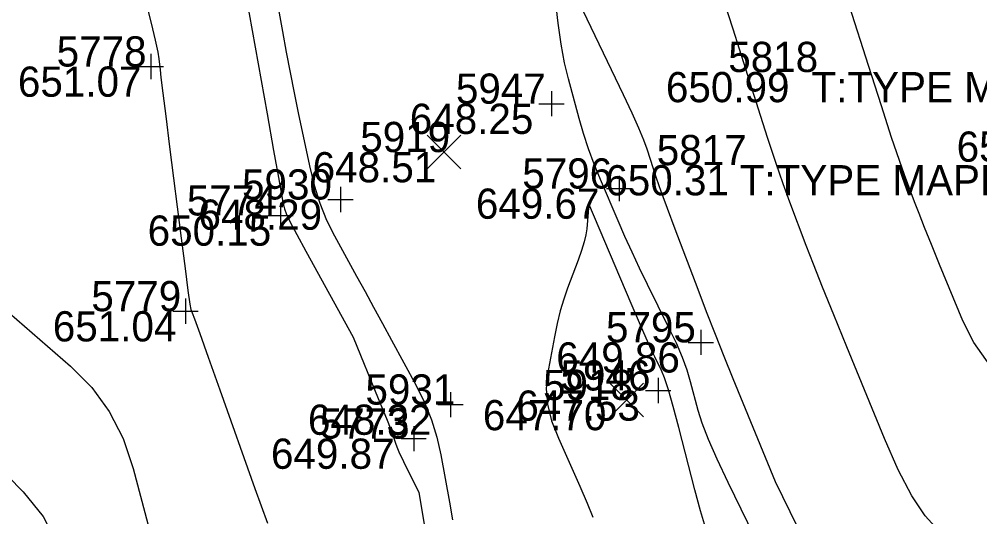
# Model space of a CAD drawing. Extents: x 2129350 to 2137777, y 657588 to 659885.
# Drawn here: x 2132814.87 to 2132853.02, y 658908.72 to 658928.49 of the extents above; entities that cross this region are included whole.
import ezdxf

# ---------------------------------------------------------------- set-up
doc = ezdxf.new("R2010")
doc.units = 0
for name, color, linetype in [('DT_X_Contour_Major', 7, 'Continuous'), ('DT_X_Contour_Minor', 7, 'Continuous'), ('SV_X_Random_Point', 7, 'Continuous'), ('SV_X_Shot_Marker', 7, 'Continuous'), ('SV_X_Text_Comment', 7, 'Continuous'), ('SV_X_Text_Elevation', 7, 'Continuous'), ('SV_X_Text_Name', 7, 'Continuous')]:
    doc.layers.add(name, color=color, linetype=linetype)

msp = doc.modelspace()

# ---------------------------------------------------------------- linework, layer by layer
at = {"layer": 'DT_X_Contour_Major'}
for points in [[(2132823.644, 658930.703), (2132824.713, 658924.723), (2132824.973, 658923.27), (2132825.166, 658922.202), (2132825.29, 658921.52), (2132825.346, 658921.223), (2132825.404, 658920.947), (2132825.473, 658920.765), (2132825.638, 658920.425), (2132825.898, 658919.928), (2132826.254, 658919.274), (2132828.135, 658915.855), (2132829.132, 658913.416), (2132829.327, 658912.937), (2132829.482, 658912.549), (2132829.599, 658912.25), (2132829.677, 658912.04), (2132829.833, 658911.601), (2132829.899, 658911.428), (2132829.98, 658911.236), (2132830.076, 658911.027), (2132830.188, 658910.8), (2132830.742, 658909.698), (2132831.737, 658903.676)], [(2132847.236, 658905.332), (2132844.904, 658910.111), (2132843.227, 658914.201), (2132842.87, 658915.08), (2132842.519, 658915.965), (2132842.172, 658916.855), (2132841.831, 658917.752), (2132840.928, 658920.149), (2132840.62, 658920.972), (2132840.373, 658921.645), (2132840.187, 658922.166), (2132840.063, 658922.536), (2132839.813, 658923.322), (2132839.684, 658923.678), (2132839.485, 658924.157), (2132839.214, 658924.758), (2132838.872, 658925.483), (2132837.114, 658929.15)]]:
    msp.add_lwpolyline(points, dxfattribs=at)
at = {"layer": 'DT_X_Contour_Minor'}
for points in [[(2132853.415, 658914.744), (2132852.783, 658915.644), (2132852.343, 658916.504), (2132851.423, 658918.746), (2132851.103, 658919.532), (2132850.831, 658920.208), (2132850.607, 658920.773), (2132850.432, 658921.229), (2132850.029, 658922.298), (2132849.827, 658922.87), (2132849.521, 658923.785), (2132849.112, 658925.043), (2132848.601, 658926.645), (2132847.098, 658931.373)], [(2132824.93, 658930.201), (2132825.324, 658928), (2132825.474, 658927.18), (2132825.629, 658926.367), (2132825.788, 658925.564), (2132825.952, 658924.769), (2132826.396, 658922.662), (2132826.583, 658921.895), (2132826.811, 658921.176), (2132827.08, 658920.505), (2132827.39, 658919.881), (2132828.27, 658918.281), (2132828.605, 658917.672), (2132828.948, 658917.044), (2132829.299, 658916.397), (2132829.659, 658915.732), (2132830.631, 658913.933), (2132830.966, 658913.255), (2132831.242, 658912.569), (2132831.459, 658911.875), (2132831.616, 658911.173), (2132831.958, 658909.293), (2132832.085, 658908.589)], [(2132819.89, 658929.221), (2132820.11, 658928.336), (2132820.272, 658927.656), (2132820.376, 658927.183), (2132820.422, 658926.916), (2132820.466, 658926.478), (2132820.502, 658926.164), (2132820.577, 658925.549), (2132820.691, 658924.635), (2132820.843, 658923.421), (2132821.303, 658919.783), (2132821.457, 658918.583), (2132821.572, 658917.711), (2132821.65, 658917.167), (2132821.69, 658916.952), (2132821.747, 658916.814), (2132821.83, 658916.585), (2132822.04, 658916), (2132822.374, 658915.061), (2132822.835, 658913.766), (2132824.229, 658909.841), (2132824.733, 658908.461)], [(2132844.331, 658907.411), (2132843.032, 658910.075), (2132842.591, 658911.003), (2132842.245, 658911.788), (2132841.993, 658912.432), (2132841.835, 658912.933), (2132841.538, 658914.079), (2132841.401, 658914.536), (2132841.211, 658915.046), (2132840.97, 658915.611), (2132840.676, 658916.229), (2132839.822, 658917.948), (2132839.509, 658918.59), (2132839.211, 658919.224), (2132838.926, 658919.852), (2132838.656, 658920.472), (2132837.954, 658922.118), (2132837.703, 658922.732), (2132837.479, 658923.34), (2132837.28, 658923.942), (2132837.108, 658924.538), (2132836.682, 658926.119), (2132836.529, 658926.759), (2132836.392, 658927.494), (2132836.27, 658928.323), (2132836.164, 658929.246)], [(2132853.21, 658906.49), (2132852.734, 658906.955), (2132851.371, 658908.18), (2132850.854, 658908.753), (2132850.325, 658909.552), (2132849.784, 658910.576), (2132849.231, 658911.827), (2132847.74, 658915.463), (2132847.22, 658916.738), (2132846.778, 658917.834), (2132846.416, 658918.751), (2132846.131, 658919.49), (2132845.479, 658921.223), (2132845.217, 658921.941), (2132844.922, 658922.794), (2132844.593, 658923.784), (2132844.231, 658924.909), (2132843.22, 658928.09), (2132842.863, 658929.187)], [(2132842.121, 658908.285), (2132841.93, 658908.948), (2132841.707, 658909.787), (2132841.067, 658912.262), (2132840.844, 658913.1), (2132840.655, 658913.757), (2132840.502, 658914.233), (2132840.382, 658914.529), (2132840.11, 658915.078), (2132839.976, 658915.364), (2132839.776, 658915.811), (2132839.511, 658916.419), (2132839.181, 658917.187), (2132837.49, 658921.151), (2132837.414, 658920.161), (2132837.38, 658919.923), (2132837.311, 658919.635), (2132837.207, 658919.296), (2132837.068, 658918.907), (2132836.65, 658917.801), (2132836.499, 658917.369), (2132836.362, 658916.901), (2132836.238, 658916.399), (2132836.127, 658915.861), (2132835.849, 658914.379), (2132835.798, 658913.804), (2132835.854, 658913.188), (2132836.016, 658912.532), (2132836.284, 658911.836), (2132837.143, 658909.927), (2132837.43, 658909.263), (2132837.649, 658908.704)], [(2132814.476, 658916.823), (2132816.912, 658914.706), (2132817.753, 658913.856), (2132818.447, 658912.895), (2132818.995, 658911.823), (2132819.396, 658910.64), (2132820.273, 658907.335)], [(2132813.808, 658910.945), (2132815.032, 658909.71), (2132815.829, 658908.733), (2132816.199, 658908.013)]]:
    msp.add_lwpolyline(points, dxfattribs=at)
at = {"layer": 'SV_X_Random_Point'}
for p, q in [((2132831.075, 658922.539), (2132832.409, 658923.875)), ((2132831.075, 658923.875), (2132832.409, 658922.539)), ((2132838.334, 658912.688), (2132839.668, 658914.022)), ((2132838.334, 658914.022), (2132839.668, 658912.688))]:
    msp.add_line(p, q, dxfattribs=at)
at = {"layer": 'SV_X_Shot_Marker'}
for p, q in [((2132820.101, 658927.106), (2132820.101, 658926.106)), ((2132819.601, 658926.606), (2132820.601, 658926.606)), ((2132820.101, 658926.606), (2132820.101, 658926.606)), ((2132836.013, 658925.629), (2132836.013, 658924.629)), ((2132835.513, 658925.129), (2132836.513, 658925.129)), ((2132836.013, 658925.129), (2132836.013, 658925.129)), ((2132838.696, 658922.258), (2132838.696, 658921.258)), ((2132827.633, 658921.822), (2132827.633, 658920.822)), ((2132838.196, 658921.758), (2132839.196, 658921.758)), ((2132838.696, 658921.758), (2132838.696, 658921.758)), ((2132825.254, 658921.188), (2132825.254, 658920.188)), ((2132827.133, 658921.322), (2132828.133, 658921.322)), ((2132827.633, 658921.322), (2132827.633, 658921.322)), ((2132824.754, 658920.688), (2132825.754, 658920.688)), ((2132825.254, 658920.688), (2132825.254, 658920.688)), ((2132821.478, 658917.384), (2132821.478, 658916.384)), ((2132820.978, 658916.884), (2132821.978, 658916.884)), ((2132821.478, 658916.884), (2132821.478, 658916.884)), ((2132841.945, 658916.147), (2132841.945, 658915.147)), ((2132841.445, 658915.647), (2132842.445, 658915.647)), ((2132841.945, 658915.647), (2132841.945, 658915.647)), ((2132840.245, 658914.234), (2132840.245, 658913.234)), ((2132831.997, 658913.674), (2132831.997, 658912.674)), ((2132839.745, 658913.734), (2132840.745, 658913.734)), ((2132840.245, 658913.734), (2132840.245, 658913.734)), ((2132831.497, 658913.174), (2132832.497, 658913.174)), ((2132831.997, 658913.174), (2132831.997, 658913.174)), ((2132830.539, 658912.323), (2132830.539, 658911.323)), ((2132830.039, 658911.823), (2132831.039, 658911.823)), ((2132830.539, 658911.823), (2132830.539, 658911.823))]:
    msp.add_line(p, q, dxfattribs=at)

# ---------------------------------------------------------------- texts
at = {"layer": 'SV_X_Text_Comment'}
for p in [(2132846.338, 658925.188), (2132843.488, 658921.488)]:
    msp.add_text('T:TYPE MAPLE T:PHOTO', height=1.2, dxfattribs=at).set_placement(p)
at = {"layer": 'SV_X_Text_Elevation'}
for s, p in [('651.07', (2132814.82, 658925.406)), ('650.99', (2132840.556, 658925.188)), ('648.25', (2132830.382, 658923.929)), ('653.61', (2132852.102, 658922.825)), ('648.51', (2132826.526, 658922.007)), ('650.31', (2132838.149, 658921.488)), ('649.67', (2132833.008, 658920.558)), ('648.29', (2132821.992, 658920.122)), ('650.15', (2132819.973, 658919.488)), ('651.04', (2132816.206, 658915.684)), ('649.86', (2132836.201, 658914.447)), ('647.53', (2132834.614, 658912.534)), ('648.32', (2132826.338, 658911.974)), ('647.70', (2132833.285, 658912.155)), ('649.87', (2132824.87, 658910.623))]:
    msp.add_text(s, height=1.2, dxfattribs=at).set_placement(p)
at = {"layer": 'SV_X_Text_Name'}
for s, p in [('5778', (2132816.359, 658926.606)), ('5818', (2132843.032, 658926.388)), ('5947', (2132832.215, 658925.129)), ('5919', (2132828.417, 658923.207)), ('5817', (2132840.191, 658922.688)), ('5796', (2132834.851, 658921.758)), ('5930', (2132823.721, 658921.322)), ('5774', (2132821.531, 658920.688)), ('5779', (2132817.736, 658916.884)), ('5795', (2132838.175, 658915.647)), ('5946', (2132836.371, 658913.734)), ('5931', (2132828.623, 658913.174)), ('5918', (2132835.676, 658913.355)), ('5773', (2132826.807, 658911.823))]:
    msp.add_text(s, height=1.2, dxfattribs=at).set_placement(p)

doc.saveas('drawing.dxf')
